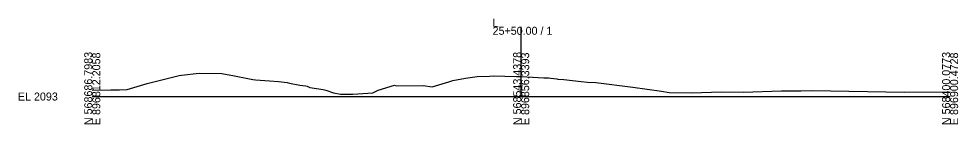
# Model space of a CAD drawing. Extents: x -26 to 1603, y -10 to 13527.
# Drawn here: x -25.7 to 302.8, y 13490.3 to 13527.2 of the extents above; entities that cross this region are included whole.
import ezdxf

# ---------------------------------------------------------------- set-up
doc = ezdxf.new("R2010")
doc.units = 0
for name, color, linetype in [('Exist XS Center Line Elevation Label', 7, 'Continuous'), ('Exist XS Ground Line', 7, 'Continuous'), ('Old_Level_63', 7, 'Continuous')]:
    doc.layers.add(name, color=color, linetype=linetype)

msp = doc.modelspace()

# ---------------------------------------------------------------- linework, layer by layer
at = {"layer": 'Exist XS Ground Line'}
for p, q in [((19.15, 13504.5), (30.36, 13507.4)), ((30.36, 13507.4), (31.17, 13507.49)), ((31.17, 13507.49), (37.39, 13508.14)), ((37.39, 13508.14), (45.28, 13508.04)), ((45.28, 13508.04), (49.74, 13507.28)), ((49.74, 13507.28), (56.12, 13506.01)), ((56.12, 13506.01), (57.09, 13505.85)), ((126.15, 13505.59), (130.49, 13506.39)), ((130.49, 13506.39), (134.65, 13507.05)), ((134.65, 13507.05), (138.98, 13507.18)), ((138.98, 13507.18), (140.17, 13507.23)), ((140.17, 13507.23), (148.34, 13507.04)), ((148.34, 13507.04), (149.95, 13507.02)), ((149.95, 13507.02), (157.92, 13506.57)), ((157.92, 13506.57), (159.53, 13506.49)), ((159.53, 13506.49), (160.35, 13506.41)), ((160.35, 13506.41), (162.48, 13506.17)), ((162.48, 13506.17), (162.84, 13506.09)), ((162.84, 13506.09), (164.87, 13505.9)), ((12.18, 13502.49), (19.15, 13504.5)), ((57.09, 13505.85), (61.95, 13505.51)), ((61.95, 13505.51), (65.17, 13505.31)), ((65.17, 13505.31), (68.12, 13504.9)), ((68.12, 13504.9), (69.02, 13504.64)), ((69.02, 13504.64), (72.64, 13503.99)), ((72.64, 13503.99), (74.73, 13503.75)), ((74.73, 13503.75), (75.1, 13503.6)), ((75.1, 13503.6), (76.04, 13503.11)), ((76.04, 13503.11), (80.81, 13502.48)), ((100.01, 13502.21), (105.7, 13504.02)), ((105.7, 13504.02), (106.26, 13503.78)), ((106.26, 13503.78), (115.75, 13503.87)), ((115.75, 13503.87), (118.86, 13503.36)), ((118.86, 13503.36), (124.66, 13505.11)), ((124.66, 13505.11), (126.15, 13505.59)), ((164.87, 13505.9), (171.01, 13505.23)), ((171.01, 13505.23), (173.23, 13505.08)), ((173.23, 13505.08), (176.12, 13504.96)), ((176.12, 13504.96), (189.01, 13503.29)), ((189.01, 13503.29), (199.05, 13501.86)), ((0, 13502.25), (6.44, 13502.34)), ((6.44, 13502.34), (9.48, 13502.37)), ((9.48, 13502.37), (12.18, 13502.49)), ((80.81, 13502.48), (81.69, 13502.26)), ((81.69, 13502.26), (84.36, 13501.35)), ((84.36, 13501.35), (86.81, 13500.85)), ((86.81, 13500.85), (91.14, 13500.82)), ((91.14, 13500.82), (98.18, 13501.32)), ((98.18, 13501.32), (100.01, 13502.21)), ((199.05, 13501.86), (201.74, 13501.38)), ((201.74, 13501.38), (209.63, 13501.25)), ((209.63, 13501.25), (219.98, 13501.61)), ((219.98, 13501.61), (227.69, 13501.52)), ((227.69, 13501.52), (241.01, 13501.95)), ((241.01, 13501.95), (247.85, 13502.03)), ((247.85, 13502.03), (251.75, 13502.11)), ((251.75, 13502.11), (283.9, 13501.58)), ((283.9, 13501.58), (300, 13501.61))]:
    msp.add_line(p, q, dxfattribs=at)
at = {"layer": 'Old_Level_63'}
for p, q in [((150, 13500), (150, 13524.41)), ((0, 13500), (150, 13500)), ((150, 13500), (300, 13500))]:
    msp.add_line(p, q, dxfattribs=at)

# ---------------------------------------------------------------- texts
at = {"layer": 'Exist XS Center Line Elevation Label'}
msp.add_text('2100.02', height=1, rotation=90, dxfattribs=at).set_placement((150.5, 13499.41))
at = {"layer": 'Old_Level_63'}
for s, p in [('L', (140, 13524.41)), ('25+50.00 / 1', (140, 13521.61)), ('EL 2093', (-26, 13498.6))]:
    msp.add_text(s, height=2.8, dxfattribs=at).set_placement(p)
for s, p in [('N 568686.7983', (0, 13490)), ('E 896812.2058', (2.8, 13490)), ('N 568543.4378', (150, 13490)), ('E 896856.3393', (152.8, 13490)), ('N 568400.0773', (300, 13490)), ('E 896900.4728', (302.8, 13490))]:
    msp.add_text(s, height=2.8, rotation=90, dxfattribs=at).set_placement(p)

doc.saveas('drawing.dxf')
